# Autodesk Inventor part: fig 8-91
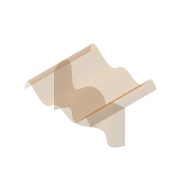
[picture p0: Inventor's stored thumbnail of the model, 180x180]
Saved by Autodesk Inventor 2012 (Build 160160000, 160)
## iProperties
Shininess: 64.0
Length Units: 11269
Angle Units: 11279
Time Units: 11290
Mass Units: 11283
Length Display Precision: 3
Angle Display Precision: 2
Compacted: True
Part Number: fig 8-91
Document SubType Name: Modeling
Created: 2003-08
Designer: Owner
Manufacturer: Standard
Standards Organization: Custom
Density: 1 g/cm^3
Material: Default
Density: 0.0
Volumn: 0.0
Area: 0.0
PropertySet Name: Model Information
Control State: 0
Master: False
Checked Out: False
Author: Owner
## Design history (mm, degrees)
sketch "Sketch1"
  geometry: 7 further points
  constraints: 7 other
  dimensions: "d0" = 80 horizontal distance of point (40, 1.742) point (-40, -4.065); "d1" = 40 horizontal distance of point (0, 0) point (-40, -4.065)
extrude_surface "ExtrusionSrf1" sketch "Sketch1" dims "d2" = 80, "d3" = 0
sketch "Sketch2"
  geometry: L1 (40, 0)-(40, -40) reference; L2 (-40, 0)-(-40, -40) reference; 7 further points
  constraints: 2 point on line, 7 other
extrude_surface "ExtrusionSrf2" sketch "Sketch2" dims "d4" = 80, "d5" = 0
sketch "Sketch3"
  geometry: 2 further points
  constraints: 4 other
sketch "Sketch4"
  geometry: L1 (52.956, 12.425)-(-10.974, 12.425); A1 r 27.841 centre (-10.974, -15.416) between (-10.974, 12.425) and (-7.259, -43.008)
  constraints: 2 end point, 2 point on circle, 1 centre point, 1 horizontal, 1 tangent
feature "Trim1"
body "Srf1"
body "Srf2"
